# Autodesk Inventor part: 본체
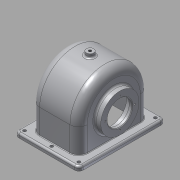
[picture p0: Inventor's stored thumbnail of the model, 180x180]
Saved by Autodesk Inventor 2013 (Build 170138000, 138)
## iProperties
Created: 2015-09
Part Number: 본체
Material: 알루미늄 6061
Document SubType Name: Modeling
Designer: user-11
Density: 2.71 g/cm^3
Mass: 656.548 g
Surface Area: 907.988 cm^2
Volume: 242.268 cm^3
Author: user-11
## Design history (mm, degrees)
sketch "스케치2"
  geometry: L1 (-70, 0)-(70, 0) reference; L2 (70, 0)-(-70, 0) reference; L3 (-57, 47)-(-57, 0); L4 (57, 47)-(57, 0); A1 r 57 centre (0, 47) between (57, 47) and (-57, 47); 4 further points
  constraints: 4 end point, 4 point on line, 3 point on circle, 2 perpendicular, 2 tangent, 1 centre point
  dimensions: "d7" = 114 diameter of A1; "d9" = 0 horizontal distance of point (0, 0) A1.centre; "d10" = 47 distance from line of L1 A1.centre
extrude "돌출2" join sketch "스케치2" stored distance "d11" = 77; taper "d12" = 0 deg
fillet "모깎기1" dims "d13" = 14
sketch "스케치4"
  geometry: C1 r 43 at (0, 0) reference; C2 r 31 at (0, 0); 1 further point
  constraints: 1 centre point, 1 coincident
  dimensions: "d15" = 62 diameter of C2
extrude "돌출3" join sketch "스케치4" distance "d17" = 10; taper "d18" = 0 deg
feature "쉘1" dims "d33" = 5
node "작업 평면1"
sketch "스케치3"
  geometry: L1 (51.504, 47)-(-69.611, 47); L2 (38.5, 90)-(38.5, 47) reference; L3 (24.5, 104)-(-24.5, 104) reference; L4 (-38.5, 47)-(-38.5, 90) reference; L5 (38.5, 84.789)-(32.793, 80); L6 (32.793, 80)-(35.5, 80); L7 (35.5, 80)-(35.5, 67); L8 (35.5, 67)-(17.5, 67); L9 (17.5, 67)-(17.5, 75); L10 (17.5, 75)-(33.5, 88.426); L11 (33.5, 88.426)-(33.5, 98); L12 (33.5, 98)-(-33.5, 98); L13 (-33.5, 98)-(-33.5, 67); L14 (-48.5, 78)-(-48.5, 16) reference; L15 (-38.5, 16)-(-38.5, 78) reference; L16 (-33.5, 67)-(-48.5, 67); L17 (-48.5, 47)-(38.5, 47); A1 r 14 centre (24.5, 90) between (38.5, 90) and (24.5, 104) reference; A2 r 14 centre (-24.5, 90) between (-24.5, 104) and (-38.5, 90) reference; 1 further point
  constraints: 24 end point, 6 perpendicular, 4 point on line, 3 parallel, 1 horizontal, 1 midpoint
  dimensions: "d14" = 47 distance from line of point (0, 0) L1; "d19" = 56 diameter of L9.end L1; "d21" = 66 diameter of L5.end L1; "d22" = 50 deg angle of L9 L10; "d23" = 16 distance between parallel lines of L9 L11; "d25" = 40 diameter of L16 L1; "d26" = 5 distance between parallel lines of L4 L13; "d27" = 6 distance between parallel lines of L5 L10; "d28" = 84 distance between parallel lines of L14 L7; "d29" = 40 diameter of L8 L1; "d30" = 6 distance between parallel lines of L3 L12; "d31" = 67 distance between parallel lines of L13 L11
  node "투영된 루프1"
sketch "스케치5"
  geometry: L1 (-27.5, 13)-(76.5, 13); L2 (76.5, 13)-(76.5, -127); L3 (76.5, -127)-(-27.5, -127); L4 (-27.5, -127)-(-27.5, 13); L5 (49, -114)-(0, -114) reference; L6 (-9, -100)-(-9, -14) reference; L7 (58, -14)-(58, -100) reference; L8 (63, -14)-(63, -100) reference; L9 (49, 0)-(0, 0) reference; L10 (-14, -100)-(-14, -14) reference; L11 (49, -114)-(0, -114) reference; L12 (49, -109)-(0, -109) reference; L13 (0, -5)-(49, -5) reference; A1 r 14 centre (49, -100) between (49, -114) and (63, -100) reference; A2 r 14 centre (49, -14) between (63, -14) and (49, 0) reference; A3 r 14 centre (0, -14) between (0, 0) and (-14, -14) reference; A4 r 14 centre (0, -100) between (-14, -100) and (0, -114) reference; A5 r 9 centre (49, -100) between (49, -109) and (58, -100) reference; A6 r 9 centre (0, -100) between (-9, -100) and (0, -109) reference; A7 r 9 centre (0, -14) between (0, -5) and (-9, -14) reference; A8 r 9 centre (49, -14) between (58, -14) and (49, -5) reference; 1 further point
  constraints: 8 end point, 2 parallel, 1 horizontal, 1 perpendicular
  dimensions: "d35" = 104 distance of L1.start L1.end; "d37" = 140 distance of L1.end L2.end; "d38" = 52 distance from line of point (24.5, -57) L4; "d39" = 70 distance from line of point (24.5, -57) L1
extrude "돌출4" join sketch "스케치5" distance "d40" = 7; taper "d41" = 0 deg
sketch "스케치6"
  geometry: 1 further point
sketch "스케치7"
  geometry: C1 r 31 at (0, 0) reference; C2 r 20 at (0, 0); 1 further point
  constraints: 1 centre point, 1 coincident
  dimensions: "d42" = 40 diameter of C2
extrude "돌출5" cut sketch "스케치7" stored distance "d44" = 102; taper "d45" = 0 deg
sketch "스케치8"
  geometry: L1 (38.5, 90)-(38.5, 47) reference; L2 (24.5, 47)-(-24.5, 47) reference; L3 (38.5, 47)-(-31.997, 47); L4 (38.5, 86.094)-(31.237, 80); L5 (31.237, 80)-(33.5, 80); L6 (33.5, 80)-(33.5, 67); L7 (33.5, 67)-(17.5, 67); L8 (17.5, 67)-(17.5, 75); L9 (17.5, 75)-(33.336, 88.288); L10 (33.5, 90)-(33.5, 47) reference; L11 (24.5, 47)-(33.5, 47) reference; L12 (24.5, 47)-(24.5, 47) reference; L13 (24.5, 47)-(33.5, 47) reference; L14 (33.5, 47)-(33.5, 47) reference; L15 (-33.5, 21)-(-33.5, 73) reference; L16 (38.5, 86.094)-(38.5, 88.288); L17 (33.336, 88.288)-(38.5, 88.288); A1 r 9 centre (24.5, 90) between (33.5, 90) and (24.5, 99) reference; 1 further point
  constraints: 18 end point, 4 parallel, 3 point on line, 2 perpendicular, 1 collinear, 1 point on circle
  dimensions: "d46" = 50 deg angle of L8 L9; "d47" = 5 distance between parallel lines of L9 L4; "d49" = 56 diameter of L8.end L3; "d50" = 66 diameter of L5 L3; "d52" = 40 diameter of L7 L3; "d53" = 67 distance between parallel lines of L15 L10 (derived); "d54" = 16 distance between parallel lines of L10 L8
revolve "회전2" sketch "스케치8" stored, may be unused: angle "d55" = 90 deg
fillet "모깎기2" dims "d62" = 7
fillet "모깎기3" dims "d63" = 1
sketch "스케치11"
  geometry: L1 (-69.5, -127)-(20.5, -127) reference; L2 (20.5, 13)-(-69.5, 13) reference; L3 (27.5, -120)-(27.5, 6) reference; C1 r 2.5 at (-24.5, 5); C2 r 2.5 at (-24.5, -119); 1 further point
  constraints: 2 centre point
  dimensions: "d73" = 5 diameter of C2; "d74" = 5 diameter of C1; "d75" = 8 distance from line of L2 C1.centre; "d76" = 8 distance from line of L1 C2.centre; "d79" = 52 distance from line of L3 C2.centre; "d80" = 52 distance from line of L3 C1.centre
extrude "돌출7" cut sketch "스케치11" stored distance "d77" = 102; taper "d78" = 0 deg
fillet "모깎기4" dims "d87" = 3
fillet "모깎기5" dims "d88" = 3
node "작업 평면2"
sketch "스케치12"
  geometry: C1 r 6 at (45, -70); 1 further point
  constraints: 1 centre point, 1 coincident
  dimensions: "d91" = 12 diameter of C1
extrude "돌출8" join sketch "스케치12" stored distance "d93" = 102; taper "d94" = 0 deg
sketch "스케치13"
  geometry: C1 r 20 at (0, 0) reference; 2 further points
  dimensions: "d95" = 24 distance of C1.centre point (-24, 0); "d96" = 0 vertical distance of C1.centre point (-24, 0)
hole "구멍1" sketch "스케치13" at (-24, 0) diameter "d97" = 2.459; stored, may be unused: countersink angle "d101" = 90 deg, drill point angle "d103" = 118 deg; dims "d98" = 6, "d99" = 4, "d100" = 2, "d102" = 8
sketch "스케치9"
  geometry: L1 (38.5, 90)-(38.5, 47) reference; L2 (37.541, 47)-(3.174, 47); L3 (33.5, 80)-(35.5, 80); L4 (35.5, 80)-(35.5, 67); L5 (17.5, 67)-(38.5, 67) reference; L6 (17.5, 75)-(33.336, 88.288) reference; L7 (33.5, 80)-(38.5, 84.195); 1 further point
  constraints: 8 end point, 3 perpendicular, 2 parallel, 2 point on line
  dimensions: "d56" = 47 distance from line of point (0, 0) L2; "d57" = 3 distance between parallel lines of L1 L4; "d59" = 66 diameter of L3 L2; "d60" = 5 horizontal distance of L7.end L3.start
revolve "회전3" sketch "스케치9" stored, may be unused: angle "d61" = 90 deg
sketch "스케치14"
  geometry: C1 r 20 at (0, 0) reference; C2 r 33 at (0, 0) reference; 1 further point
extrude "돌출9" cut sketch "스케치14" distance "d104" = 3; taper "d105" = 0 deg
sketch "스케치15"
  geometry: C1 r 20 at (0, 0) reference; C2 r 33 at (0, 0) reference; 1 further point
fillet "모깎기7" dims "d106" = 0.5
sketch "스케치16"
  geometry: C1 r 20 at (0, 0) reference; 2 further points
  dimensions: "d108" = 28 distance of C1.centre point (0, 28); "d109" = 0 horizontal distance of C1.centre point (0, 28)
hole "구멍2" sketch "스케치16" at (0, 28) diameter "d110" = 2.459; stored, may be unused: countersink angle "d114" = 90 deg, drill point angle "d116" = 118 deg; dims "d111" = 7, "d112" = 4, "d113" = 2, "d115" = 9
fillet "모깎기8" dims "d120" = 3
sketch "스케치17"
  geometry: C1 r 6 at (0, 0) reference; 1 further point
  constraints: 1 coincident
hole "구멍3" sketch "스케치17" at (0, 0) diameter "d121" = 4.459; stored, may be unused: countersink angle "d125" = 90 deg, drill point angle "d127" = 118 deg; dims "d122" = 7, "d123" = 4, "d124" = 2, "d126" = 9
chamfer "모따기1" distance "d128" = 1; stored, may be unused: second distance "d129" = 2, angle "d130" = 45 deg
node "솔리드1"
pattern_linear "직사각형 패턴1" dims "d83" = 44
pattern_linear "직사각형 패턴2" dims "d86" = 44
pattern_circular "원형 패턴1" dims angle "d118" = 360 deg
pattern_circular "원형 패턴2" dims angle "d132" = 360 deg
node "투영된 루프2"
node "투영된 루프3"
other parameters: "d34" = -7
